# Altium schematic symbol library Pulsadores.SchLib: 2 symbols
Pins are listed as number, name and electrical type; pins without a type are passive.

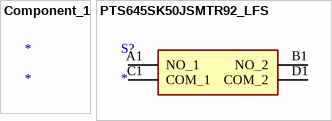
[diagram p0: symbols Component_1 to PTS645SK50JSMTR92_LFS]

## Component_1
designator *

## PTS645SK50JSMTR92_LFS
designator S?
Switch; Manufacturer_Name: C & K COMPONENTS; Manufacturer_Part_Number: PTS645SK50JSMTR92 LFS; Description: Tactile Switches 50mA 12VDC
footprint PTS645SK50JSMTR92LFS
pins: A1 NO_1, B1 NO_2, C1 COM_1, D1 COM_2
